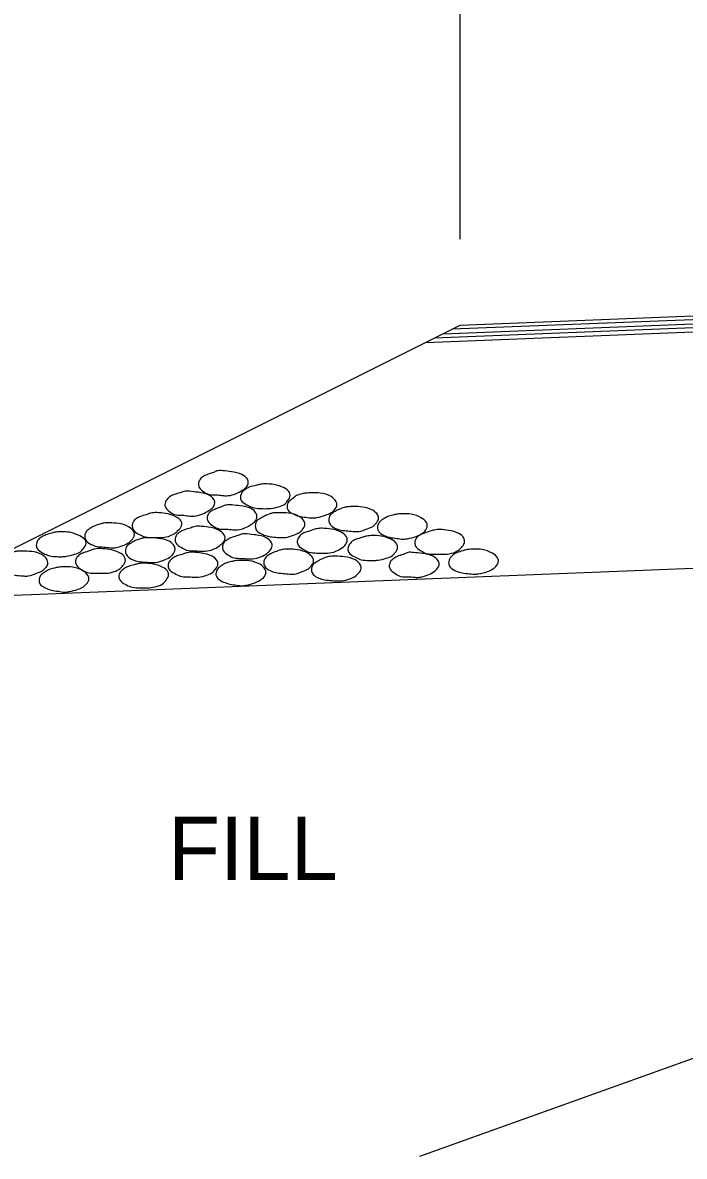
# Model space of a CAD drawing. Extents: x 3287 to 1767681, y -265 to 581440.
# Drawn here: x 3324 to 3336.53, y 48.6 to 70.04 of the extents above; entities that cross this region are included whole.
import ezdxf

# ---------------------------------------------------------------- set-up
doc = ezdxf.new("R2010")
doc.units = 0
doc.layers.add('R_Border PE', color=7, linetype='Continuous')

msp = doc.modelspace()

# ---------------------------------------------------------------- linework, layer by layer
at = {"layer": 'R_Border PE'}
for p, q in [((3332.286, 65.948), (3332.286, 96.509)), ((3331.966, 64.158), (3460.793, 69.3)), ((3332.136, 64.247), (3460.643, 69.373)), ((3332.286, 64.318), (3460.506, 69.441)), ((3331.631, 63.991), (3461.081, 69.155)), ((3331.799, 64.078), (3460.936, 69.227)), ((3307.45, 51.908), (3332.286, 64.318)), ((3321.917, 59.136), (3372.148, 61.138)), ((3361.044, 59.148), (3331.515, 48.595))]:
    msp.add_line(p, q, dxfattribs=at)
for points in [[(3327.791, 61.566), (3327.956, 61.547), (3328.155, 61.492), (3328.261, 61.403), (3328.276, 61.343), (3328.226, 61.243), (3328.161, 61.196), (3328.048, 61.133), (3327.893, 61.094), (3327.807, 61.094), (3327.687, 61.107), (3327.543, 61.115), (3327.444, 61.157), (3327.346, 61.249), (3327.333, 61.31), (3327.362, 61.404), (3327.435, 61.463), (3327.506, 61.497), (3327.618, 61.534), (3327.682, 61.561), (3327.791, 61.566)], [(3327.158, 61.179), (3327.328, 61.157), (3327.52, 61.11), (3327.627, 61.016), (3327.643, 60.958), (3327.59, 60.856), (3327.529, 60.812), (3327.417, 60.752), (3327.257, 60.707), (3327.176, 60.707), (3327.053, 60.722), (3326.912, 60.73), (3326.809, 60.773), (3326.715, 60.864), (3326.697, 60.927), (3326.731, 61.018), (3326.805, 61.082), (3326.877, 61.115), (3326.987, 61.15), (3327.053, 61.173), (3327.158, 61.179)], [(3328.591, 61.317), (3328.761, 61.304), (3328.957, 61.239), (3329.054, 61.154), (3329.069, 61.103), (3329.018, 60.993), (3328.972, 60.942), (3328.855, 60.885), (3328.701, 60.854), (3328.616, 60.848), (3328.491, 60.851), (3328.349, 60.874), (3328.248, 60.922), (3328.143, 61), (3328.127, 61.066), (3328.156, 61.154), (3328.237, 61.226), (3328.305, 61.259), (3328.42, 61.289), (3328.488, 61.304), (3328.591, 61.317)], [(3329.473, 61.145), (3329.638, 61.141), (3329.843, 61.076), (3329.937, 60.979), (3329.955, 60.922), (3329.9, 60.819), (3329.847, 60.773), (3329.737, 60.725), (3329.575, 60.68), (3329.488, 60.673), (3329.365, 60.684), (3329.23, 60.707), (3329.125, 60.749), (3329.027, 60.828), (3329.01, 60.89), (3329.043, 60.982), (3329.117, 61.04), (3329.187, 61.094), (3329.298, 61.128), (3329.368, 61.141), (3329.473, 61.145)], [(3327.962, 60.919), (3328.127, 60.9), (3328.328, 60.851), (3328.425, 60.754), (3328.439, 60.699), (3328.391, 60.595), (3328.331, 60.55), (3328.226, 60.489), (3328.067, 60.45), (3327.981, 60.45), (3327.855, 60.461), (3327.716, 60.468), (3327.614, 60.516), (3327.514, 60.605), (3327.496, 60.667), (3327.527, 60.76), (3327.605, 60.817), (3327.679, 60.851), (3327.791, 60.893), (3327.855, 60.916), (3327.962, 60.919)], [(3326.542, 60.773), (3326.708, 60.757), (3326.902, 60.696), (3327.004, 60.613), (3327.019, 60.552), (3326.964, 60.453), (3326.906, 60.398), (3326.804, 60.338), (3326.644, 60.304), (3326.561, 60.304), (3326.433, 60.301), (3326.294, 60.324), (3326.187, 60.372), (3326.089, 60.461), (3326.077, 60.515), (3326.107, 60.617), (3326.178, 60.673), (3326.255, 60.707), (3326.372, 60.743), (3326.433, 60.764), (3326.542, 60.773)], [(3328.871, 60.77), (3329.036, 60.764), (3329.24, 60.702), (3329.334, 60.607), (3329.348, 60.55), (3329.298, 60.447), (3329.25, 60.401), (3329.132, 60.346), (3328.978, 60.301), (3328.892, 60.301), (3328.763, 60.309), (3328.629, 60.332), (3328.525, 60.369), (3328.421, 60.456), (3328.409, 60.519), (3328.434, 60.613), (3328.514, 60.67), (3328.587, 60.709), (3328.698, 60.754), (3328.763, 60.769), (3328.871, 60.77)], [(3330.266, 60.888), (3330.437, 60.879), (3330.631, 60.817), (3330.727, 60.725), (3330.744, 60.663), (3330.689, 60.565), (3330.646, 60.519), (3330.528, 60.468), (3330.369, 60.416), (3330.287, 60.416), (3330.162, 60.427), (3330.029, 60.443), (3329.916, 60.482), (3329.813, 60.571), (3329.798, 60.633), (3329.829, 60.727), (3329.903, 60.785), (3329.981, 60.828), (3330.093, 60.87), (3330.162, 60.882), (3330.266, 60.888)], [(3331.193, 60.748), (3331.359, 60.743), (3331.552, 60.673), (3331.649, 60.587), (3331.665, 60.529), (3331.618, 60.421), (3331.561, 60.377), (3331.453, 60.324), (3331.291, 60.28), (3331.209, 60.272), (3331.086, 60.285), (3330.947, 60.306), (3330.838, 60.346), (3330.738, 60.427), (3330.722, 60.492), (3330.754, 60.583), (3330.827, 60.649), (3330.905, 60.693), (3331.016, 60.727), (3331.087, 60.743), (3331.193, 60.748)], [(3325.646, 60.579), (3325.817, 60.568), (3326.01, 60.506), (3326.108, 60.413), (3326.12, 60.356), (3326.071, 60.257), (3326.018, 60.209), (3325.908, 60.152), (3325.749, 60.109), (3325.665, 60.109), (3325.54, 60.121), (3325.406, 60.134), (3325.298, 60.173), (3325.194, 60.262), (3325.181, 60.327), (3325.209, 60.416), (3325.283, 60.476), (3325.358, 60.519), (3325.476, 60.558), (3325.54, 60.574), (3325.646, 60.579)], [(3327.349, 60.516), (3327.517, 60.5), (3327.719, 60.44), (3327.82, 60.35), (3327.838, 60.295), (3327.784, 60.191), (3327.729, 60.147), (3327.611, 60.079), (3327.459, 60.045), (3327.372, 60.045), (3327.245, 60.049), (3327.108, 60.063), (3327.004, 60.117), (3326.906, 60.199), (3326.891, 60.265), (3326.924, 60.356), (3327, 60.416), (3327.071, 60.45), (3327.176, 60.482), (3327.244, 60.506), (3327.349, 60.516)], [(3324.727, 60.409), (3324.893, 60.401), (3325.087, 60.332), (3325.191, 60.251), (3325.206, 60.198), (3325.149, 60.088), (3325.1, 60.033), (3324.984, 59.984), (3324.832, 59.947), (3324.751, 59.939), (3324.618, 59.942), (3324.476, 59.968), (3324.377, 60.015), (3324.277, 60.094), (3324.262, 60.155), (3324.292, 60.251), (3324.366, 60.317), (3324.442, 60.35), (3324.554, 60.387), (3324.617, 60.401), (3324.727, 60.409)], [(3326.414, 60.298), (3326.576, 60.286), (3326.778, 60.23), (3326.878, 60.133), (3326.891, 60.076), (3326.841, 59.976), (3326.791, 59.929), (3326.674, 59.874), (3326.521, 59.829), (3326.43, 59.829), (3326.304, 59.837), (3326.166, 59.856), (3326.065, 59.895), (3325.963, 59.984), (3325.948, 60.045), (3325.979, 60.138), (3326.055, 60.198), (3326.128, 60.238), (3326.239, 60.28), (3326.304, 60.295), (3326.414, 60.298)], [(3328.256, 60.372), (3328.421, 60.35), (3328.616, 60.298), (3328.714, 60.204), (3328.729, 60.147), (3328.677, 60.045), (3328.629, 59.999), (3328.514, 59.939), (3328.358, 59.898), (3328.271, 59.898), (3328.148, 59.906), (3328.006, 59.918), (3327.899, 59.968), (3327.802, 60.055), (3327.787, 60.12), (3327.813, 60.207), (3327.889, 60.267), (3327.967, 60.304), (3328.083, 60.341), (3328.148, 60.366), (3328.256, 60.372)], [(3329.677, 60.477), (3329.847, 60.463), (3330.036, 60.401), (3330.135, 60.312), (3330.149, 60.261), (3330.102, 60.151), (3330.047, 60.104), (3329.934, 60.042), (3329.774, 60.005), (3329.693, 60.005), (3329.57, 60.008), (3329.431, 60.024), (3329.324, 60.076), (3329.219, 60.159), (3329.203, 60.23), (3329.237, 60.317), (3329.311, 60.379), (3329.386, 60.409), (3329.497, 60.447), (3329.575, 60.469), (3329.677, 60.477)], [(3330.628, 60.338), (3330.793, 60.33), (3330.992, 60.262), (3331.089, 60.176), (3331.104, 60.125), (3331.053, 60.011), (3331.005, 59.963), (3330.887, 59.91), (3330.732, 59.874), (3330.649, 59.866), (3330.523, 59.868), (3330.381, 59.893), (3330.28, 59.942), (3330.18, 60.018), (3330.162, 60.088), (3330.193, 60.176), (3330.266, 60.246), (3330.345, 60.277), (3330.455, 60.312), (3330.52, 60.33), (3330.628, 60.338)], [(3331.904, 60.456), (3332.069, 60.437), (3332.262, 60.377), (3332.359, 60.286), (3332.372, 60.233), (3332.327, 60.13), (3332.275, 60.076), (3332.16, 60.015), (3331.998, 59.986), (3331.917, 59.986), (3331.794, 59.989), (3331.655, 59.999), (3331.545, 60.052), (3331.443, 60.138), (3331.43, 60.201), (3331.458, 60.293), (3331.536, 60.353), (3331.612, 60.387), (3331.722, 60.421), (3331.799, 60.443), (3331.904, 60.456)], [(3325.482, 60.094), (3325.644, 60.076), (3325.835, 60.015), (3325.935, 59.929), (3325.948, 59.871), (3325.903, 59.77), (3325.848, 59.714), (3325.739, 59.657), (3325.574, 59.626), (3325.492, 59.626), (3325.364, 59.628), (3325.227, 59.641), (3325.121, 59.69), (3325.023, 59.78), (3325.003, 59.843), (3325.036, 59.935), (3325.108, 59.992), (3325.188, 60.024), (3325.299, 60.06), (3325.369, 60.084), (3325.482, 60.094)], [(3329.039, 60.083), (3329.206, 60.07), (3329.403, 60.005), (3329.497, 59.916), (3329.513, 59.856), (3329.46, 59.758), (3329.416, 59.711), (3329.302, 59.66), (3329.143, 59.609), (3329.057, 59.609), (3328.931, 59.623), (3328.795, 59.638), (3328.69, 59.675), (3328.583, 59.766), (3328.57, 59.829), (3328.601, 59.918), (3328.677, 59.981), (3328.753, 60.018), (3328.865, 60.06), (3328.931, 60.076), (3329.039, 60.083)], [(3332.539, 60.079), (3332.704, 60.075), (3332.899, 60.003), (3332.995, 59.919), (3333.012, 59.861), (3332.964, 59.754), (3332.907, 59.707), (3332.804, 59.657), (3332.637, 59.615), (3332.556, 59.609), (3332.433, 59.62), (3332.293, 59.641), (3332.184, 59.678), (3332.084, 59.762), (3332.069, 59.825), (3332.1, 59.916), (3332.173, 59.986), (3332.252, 60.024), (3332.365, 60.06), (3332.435, 60.075), (3332.539, 60.079)], [(3324.004, 60.045), (3324.169, 60.036), (3324.369, 59.978), (3324.466, 59.879), (3324.481, 59.825), (3324.432, 59.719), (3324.379, 59.675), (3324.267, 59.626), (3324.11, 59.575), (3324.025, 59.575), (3323.895, 59.584), (3323.758, 59.609), (3323.654, 59.643), (3323.554, 59.728), (3323.541, 59.795), (3323.568, 59.885), (3323.648, 59.945), (3323.722, 59.989), (3323.832, 60.026), (3323.895, 60.042), (3324.004, 60.045)], [(3327.232, 60.024), (3327.396, 60.005), (3327.59, 59.947), (3327.687, 59.858), (3327.702, 59.804), (3327.656, 59.703), (3327.605, 59.648), (3327.491, 59.588), (3327.331, 59.554), (3327.245, 59.554), (3327.119, 59.557), (3326.987, 59.573), (3326.878, 59.626), (3326.773, 59.707), (3326.757, 59.777), (3326.791, 59.863), (3326.869, 59.926), (3326.941, 59.96), (3327.053, 59.992), (3327.124, 60.015), (3327.232, 60.024)], [(3328.134, 59.866), (3328.295, 59.861), (3328.498, 59.795), (3328.591, 59.707), (3328.609, 59.651), (3328.561, 59.541), (3328.504, 59.5), (3328.4, 59.447), (3328.237, 59.398), (3328.15, 59.39), (3328.024, 59.405), (3327.889, 59.429), (3327.781, 59.473), (3327.679, 59.549), (3327.663, 59.615), (3327.695, 59.706), (3327.773, 59.774), (3327.846, 59.816), (3327.959, 59.846), (3328.025, 59.861), (3328.134, 59.866)], [(3329.932, 59.947), (3330.101, 59.939), (3330.301, 59.877), (3330.398, 59.782), (3330.414, 59.725), (3330.363, 59.626), (3330.314, 59.578), (3330.198, 59.521), (3330.042, 59.481), (3329.957, 59.481), (3329.829, 59.489), (3329.69, 59.51), (3329.589, 59.544), (3329.484, 59.633), (3329.471, 59.696), (3329.5, 59.785), (3329.58, 59.846), (3329.651, 59.887), (3329.761, 59.932), (3329.829, 59.945), (3329.932, 59.947)], [(3331.401, 60.018), (3331.576, 60), (3331.77, 59.95), (3331.874, 59.855), (3331.891, 59.801), (3331.84, 59.696), (3331.783, 59.651), (3331.663, 59.588), (3331.511, 59.549), (3331.427, 59.549), (3331.301, 59.56), (3331.159, 59.567), (3331.057, 59.62), (3330.961, 59.706), (3330.945, 59.77), (3330.976, 59.858), (3331.05, 59.919), (3331.12, 59.953), (3331.235, 59.992), (3331.299, 60.018), (3331.401, 60.018)], [(3324.785, 59.746), (3324.952, 59.74), (3325.146, 59.67), (3325.24, 59.584), (3325.259, 59.525), (3325.209, 59.418), (3325.155, 59.371), (3325.05, 59.322), (3324.887, 59.279), (3324.801, 59.269), (3324.677, 59.285), (3324.542, 59.308), (3324.432, 59.351), (3324.329, 59.428), (3324.314, 59.492), (3324.343, 59.581), (3324.423, 59.648), (3324.495, 59.69), (3324.605, 59.722), (3324.68, 59.74), (3324.785, 59.746)], [(3326.289, 59.816), (3326.456, 59.804), (3326.66, 59.736), (3326.754, 59.654), (3326.767, 59.604), (3326.718, 59.492), (3326.67, 59.437), (3326.55, 59.381), (3326.396, 59.353), (3326.312, 59.348), (3326.187, 59.351), (3326.043, 59.369), (3325.943, 59.418), (3325.841, 59.5), (3325.825, 59.562), (3325.857, 59.654), (3325.932, 59.719), (3326.008, 59.754), (3326.115, 59.788), (3326.184, 59.804), (3326.289, 59.816)]]:
    msp.add_spline(points, degree=3, dxfattribs=at)

# ---------------------------------------------------------------- texts
msp.add_text('FILL', height=1.2, dxfattribs=at).set_placement((3326.759, 53.82))

doc.saveas('drawing.dxf')
